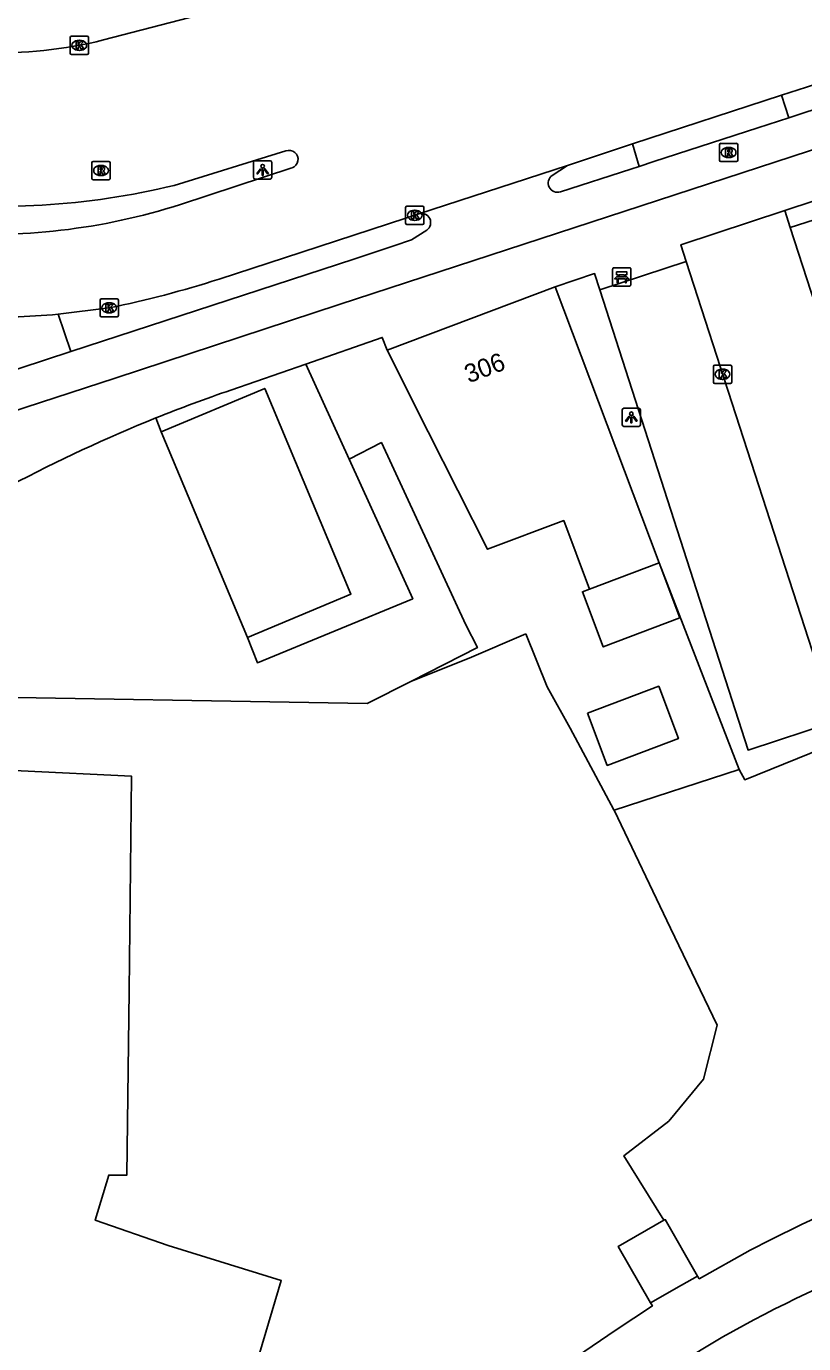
# Model space of a CAD drawing. Extents: x 163010 to 163853, y 382793 to 383982.
# Drawn here: x 163172.3 to 163214.8, y 383532.5 to 383604.5 of the extents above; entities that cross this region are included whole.
import ezdxf

# ---------------------------------------------------------------- set-up
doc = ezdxf.new("R2010")
doc.units = 0
for name, color, linetype in [('IMGEO_Bank', 7, 'Continuous'), ('IMGEO_Berm_open', 7, 'Continuous'), ('IMGEO_Fietspad_open', 7, 'Continuous'), ('IMGEO_Groenvoorziening', 7, 'Continuous'), ('IMGEO_Hek', 7, 'Continuous'), ('IMGEO_Kolk', 7, 'Continuous'), ('IMGEO_Lage_trafo', 7, 'Continuous'), ('IMGEO_Lichtpunt', 7, 'Continuous'), ('IMGEO_Muur', 7, 'Continuous'), ('IMGEO_Pand', 7, 'Continuous'), ('IMGEO_Pand_nummerreeks', 7, 'Continuous'), ('IMGEO_Parkeervlak_open', 7, 'Continuous'), ('IMGEO_Rijbaan_lokaal_gesloten', 7, 'Continuous'), ('IMGEO_Rijbaan_lokaal_open', 7, 'Continuous'), ('IMGEO_Rioolput', 7, 'Continuous'), ('IMGEO_Verkeerseiland_open', 7, 'Continuous'), ('IMGEO_Voetpad_halfverhard', 7, 'Continuous'), ('IMGEO_Voetpad_open', 7, 'Continuous')]:
    doc.layers.add(name, color=color, linetype=linetype)

msp = doc.modelspace()

# ---------------------------------------------------------------- linework, layer by layer
at = {"layer": 'IMGEO_Bank'}
for p, q in [((163204.37, 383590.379), (163204.37, 383591.22)), ((163204.37, 383591.22), (163204.37, 383590.379)), ((163204.445, 383591.304), (163205.286, 383591.304)), ((163205.286, 383591.304), (163204.445, 383591.304)), ((163205.067, 383590.702), (163204.674, 383590.702)), ((163204.679, 383590.81), (163204.679, 383590.916)), ((163204.723, 383590.916), (163204.723, 383590.81)), ((163205.011, 383590.922), (163204.729, 383590.922)), ((163204.729, 383590.804), (163205.011, 383590.804)), ((163205.017, 383590.81), (163205.017, 383590.916)), ((163205.061, 383590.916), (163205.061, 383590.81)), ((163205.37, 383591.229), (163205.37, 383590.388)), ((163205.37, 383590.388), (163205.37, 383591.229)), ((163205.295, 383590.304), (163204.454, 383590.304)), ((163204.454, 383590.304), (163205.295, 383590.304))]:
    msp.add_line(p, q, dxfattribs=at)
for points in [[(163204.617, 383590.702), (163204.475, 383590.702), (163204.587, 383590.804), (163204.673, 383590.804)], [(163204.673, 383590.922), (163204.587, 383590.922), (163204.587, 383591.083), (163205.15, 383591.083), (163205.15, 383590.922), (163205.067, 383590.922)], [(163204.667, 383590.695), (163204.667, 383590.488), (163204.624, 383590.488), (163204.624, 383590.695)], [(163205.067, 383590.804), (163205.15, 383590.804), (163205.262, 383590.702), (163205.123, 383590.702)], [(163205.117, 383590.695), (163205.117, 383590.488), (163205.073, 383590.488), (163205.073, 383590.695)]]:
    msp.add_lwpolyline(points, dxfattribs=at)
for centre, radius, start, end in [((163204.448, 383591.226), 0.0779, 92.4484, 184.28452), ((163204.448, 383591.226), 0.0779, 92.4484, 184.28452), ((163204.617, 383590.695), 0.00671, 2.89567, 87.10433), ((163204.674, 383590.695), 0.00671, 92.89567, 177.10433), ((163204.672, 383590.915), 0.00671, 2.89567, 87.10433), ((163204.672, 383590.811), 0.00671, 272.89567, 357.10433), ((163204.729, 383590.915), 0.00671, 92.89567, 177.10433), ((163204.729, 383590.811), 0.00671, 182.89567, 267.10433), ((163205.011, 383590.915), 0.00671, 2.89567, 87.10433), ((163205.011, 383590.811), 0.00671, 272.89567, 357.10433), ((163205.068, 383590.915), 0.00671, 92.89567, 177.10433), ((163205.068, 383590.811), 0.00671, 182.89567, 267.10433), ((163205.066, 383590.695), 0.00671, 2.89567, 87.10433), ((163205.123, 383590.695), 0.00671, 92.89567, 177.10433), ((163205.292, 383591.226), 0.0779, 2.4484, 94.28452), ((163205.292, 383591.226), 0.0779, 2.4484, 94.28452), ((163204.448, 383590.382), 0.0779, 182.4484, 274.28452), ((163204.448, 383590.382), 0.0779, 182.4484, 274.28452), ((163205.292, 383590.382), 0.0779, 272.4484, 4.28452), ((163205.292, 383590.382), 0.0779, 272.4484, 4.28452)]:
    msp.add_arc(centre, radius, start, end, dxfattribs=at)
at = {"layer": 'IMGEO_Berm_open'}
msp.add_lwpolyline([(163213.597, 383600.731), (163214, 383599.504)], dxfattribs=at)
at = {"layer": 'IMGEO_Fietspad_open'}
for points in [[(163227.273, 383603.884), (163214, 383599.504)], [(163165.737, 383581.534), (163177.201, 383585.275), (163189.429, 383589.292), (163227.938, 383601.879)], [(163214, 383599.504), (163212.305, 383598.953), (163206.623, 383597.104), (163205.825, 383596.845)], [(163201.071, 383596.353), (163201.91, 383596.897)], [(163205.825, 383596.845), (163205.366, 383596.686), (163201.515, 383595.458)], [(163194.216, 383593.356), (163193.389, 383592.83), (163192.424, 383592.497), (163190.238, 383591.768), (163174.785, 383586.731)], [(163174.785, 383586.731), (163165.182, 383583.588)]]:
    msp.add_lwpolyline(points, dxfattribs=at)
for centre, radius, start, end in [((163201.355, 383595.936), 0.504, 124.23922, 288.53182), ((163193.925, 383593.772), 0.508, 304.98045, 106.77094)]:
    msp.add_arc(centre, radius, start, end, dxfattribs=at)
at = {"layer": 'IMGEO_Groenvoorziening'}
for points in [[(163179.716, 383582.349), (163184.42, 383571.112)], [(163167.542, 383567.909), (163190.955, 383567.498), (163193.383, 383568.73), (163196.982, 383570.557), (163196.354, 383571.794), (163191.745, 383581.753), (163189.98, 383580.853)], [(163206.912, 383575.186), (163211.278, 383563.895)], [(163211.278, 383563.895), (163211.588, 383563.335), (163224.444, 383568.537)], [(163207.169, 383539.271), (163204.989, 383542.801), (163207.436, 383544.678), (163209.327, 383546.99), (163210.082, 383549.931), (163207.536, 383555.238), (163204.446, 383561.681), (163211.278, 383563.895)]]:
    msp.add_lwpolyline(points, dxfattribs=at)
at = {"layer": 'IMGEO_Hek'}
msp.add_lwpolyline([(163204.439, 383561.696), (163204.446, 383561.681), (163207.536, 383555.238), (163210.082, 383549.931), (163209.327, 383546.99), (163207.436, 383544.678), (163204.989, 383542.801), (163207.169, 383539.271)], dxfattribs=at)
at = {"layer": 'IMGEO_Kolk'}
for p, q in [((163174.74, 383603.032), (163174.74, 383603.884)), ((163174.815, 383603.958), (163175.667, 383603.958)), ((163175.228, 383603.738), (163175.253, 383603.738)), ((163175.741, 383603.884), (163175.741, 383603.032)), ((163175.667, 383602.958), (163174.815, 383602.958)), ((163175.251, 383603.178), (163175.226, 383603.178)), ((163193.064, 383593.747), (163193.064, 383594.599)), ((163193.139, 383594.673), (163193.991, 383594.673)), ((163193.552, 383594.453), (163193.577, 383594.453)), ((163194.065, 383594.599), (163194.065, 383593.747)), ((163193.991, 383593.673), (163193.139, 383593.673)), ((163193.575, 383593.893), (163193.55, 383593.893)), ((163176.374, 383588.692), (163176.374, 383589.544)), ((163176.449, 383589.618), (163177.301, 383589.618)), ((163176.862, 383589.398), (163176.887, 383589.398)), ((163177.375, 383589.544), (163177.375, 383588.692)), ((163177.301, 383588.618), (163176.449, 383588.618)), ((163176.885, 383588.838), (163176.86, 383588.838)), ((163209.874, 383585.063), (163209.874, 383585.915)), ((163209.949, 383585.989), (163210.801, 383585.989)), ((163210.362, 383585.769), (163210.387, 383585.769)), ((163210.875, 383585.915), (163210.875, 383585.063)), ((163210.801, 383584.989), (163209.949, 383584.989)), ((163210.385, 383585.209), (163210.36, 383585.209))]:
    msp.add_line(p, q, dxfattribs=at)
for points in [[(163174.74, 383603.032), (163174.74, 383603.884)], [(163174.815, 383603.958), (163175.667, 383603.958)], [(163175.061, 383603.658), (163175.184, 383603.658), (163175.184, 383603.507), (163175.314, 383603.658), (163175.478, 383603.658), (163175.332, 383603.507), (163175.485, 383603.258), (163175.333, 383603.258), (163175.248, 383603.422), (163175.184, 383603.355), (163175.184, 383603.258), (163175.061, 383603.258), (163175.061, 383603.658)], [(163175.741, 383603.884), (163175.741, 383603.032)], [(163175.667, 383602.958), (163174.815, 383602.958)], [(163193.064, 383593.747), (163193.064, 383594.599)], [(163193.139, 383594.673), (163193.991, 383594.673)], [(163193.385, 383594.373), (163193.508, 383594.373), (163193.508, 383594.222), (163193.638, 383594.373), (163193.802, 383594.373), (163193.656, 383594.222), (163193.809, 383593.973), (163193.657, 383593.973), (163193.572, 383594.137), (163193.508, 383594.07), (163193.508, 383593.973), (163193.385, 383593.973), (163193.385, 383594.373)], [(163194.065, 383594.599), (163194.065, 383593.747)], [(163193.991, 383593.673), (163193.139, 383593.673)], [(163176.374, 383588.692), (163176.374, 383589.544)], [(163176.449, 383589.618), (163177.301, 383589.618)], [(163176.695, 383589.318), (163176.818, 383589.318), (163176.818, 383589.167), (163176.948, 383589.318), (163177.112, 383589.318), (163176.966, 383589.167), (163177.119, 383588.918), (163176.967, 383588.918), (163176.882, 383589.082), (163176.818, 383589.015), (163176.818, 383588.918), (163176.695, 383588.918), (163176.695, 383589.318)], [(163177.375, 383589.544), (163177.375, 383588.692)], [(163177.301, 383588.618), (163176.449, 383588.618)], [(163209.874, 383585.063), (163209.874, 383585.915)], [(163209.949, 383585.989), (163210.801, 383585.989)], [(163210.195, 383585.689), (163210.318, 383585.689), (163210.318, 383585.538), (163210.448, 383585.689), (163210.612, 383585.689), (163210.466, 383585.538), (163210.619, 383585.289), (163210.467, 383585.289), (163210.382, 383585.453), (163210.318, 383585.386), (163210.318, 383585.289), (163210.195, 383585.289), (163210.195, 383585.689)], [(163210.875, 383585.915), (163210.875, 383585.063)], [(163210.801, 383584.989), (163209.949, 383584.989)]]:
    msp.add_lwpolyline(points, dxfattribs=at)
for centre, start, end in [((163174.817, 383603.882), 91.55205, 178.44795), ((163174.817, 383603.882), 91.55205, 178.44795), ((163175.665, 383603.882), 1.55205, 88.44795), ((163175.665, 383603.882), 1.55205, 88.44795), ((163174.817, 383603.034), 181.55205, 268.44795), ((163174.817, 383603.034), 181.55205, 268.44795), ((163175.665, 383603.034), 271.55205, 358.44795), ((163175.665, 383603.034), 271.55205, 358.44795), ((163193.141, 383594.597), 91.55205, 178.44795), ((163193.141, 383594.597), 91.55205, 178.44795), ((163193.989, 383594.597), 1.55205, 88.44795), ((163193.989, 383594.597), 1.55205, 88.44795), ((163193.141, 383593.749), 181.55205, 268.44795), ((163193.141, 383593.749), 181.55205, 268.44795), ((163193.989, 383593.749), 271.55205, 358.44795), ((163193.989, 383593.749), 271.55205, 358.44795), ((163176.451, 383589.542), 91.55205, 178.44795), ((163176.451, 383589.542), 91.55205, 178.44795), ((163177.299, 383589.542), 1.55205, 88.44795), ((163177.299, 383589.542), 1.55205, 88.44795), ((163176.451, 383588.694), 181.55205, 268.44795), ((163176.451, 383588.694), 181.55205, 268.44795), ((163177.299, 383588.694), 271.55205, 358.44795), ((163177.299, 383588.694), 271.55205, 358.44795), ((163209.951, 383585.913), 91.55205, 178.44795), ((163209.951, 383585.913), 91.55205, 178.44795), ((163210.799, 383585.913), 1.55205, 88.44795), ((163210.799, 383585.913), 1.55205, 88.44795), ((163209.951, 383585.065), 181.55205, 268.44795), ((163209.951, 383585.065), 181.55205, 268.44795), ((163210.799, 383585.065), 271.55205, 358.44795), ((163210.799, 383585.065), 271.55205, 358.44795)]:
    msp.add_arc(centre, 0.0765, start, end, dxfattribs=at)
for centre, major_axis, ratio, start_param, end_param in [((163175.227, 383603.458), (-0.387, 0.002), 0.722429, 4.712389, 7.853982), ((163175.252, 383603.458), (-0.39, 0.002), 0.717154, 1.570796, 4.712389), ((163193.551, 383594.173), (-0.387, 0.002), 0.722429, 4.712389, 7.853982), ((163193.576, 383594.173), (-0.39, 0.002), 0.717154, 1.570796, 4.712389), ((163176.861, 383589.118), (-0.387, 0.002), 0.722429, 4.712389, 7.853982), ((163176.886, 383589.118), (-0.39, 0.002), 0.717154, 1.570796, 4.712389), ((163210.361, 383585.489), (-0.387, 0.002), 0.722429, 4.712389, 7.853982), ((163210.386, 383585.489), (-0.39, 0.002), 0.717154, 1.570796, 4.712389)]:
    msp.add_ellipse(centre, major_axis=major_axis, ratio=ratio, start_param=start_param, end_param=end_param, dxfattribs=at)
at = {"layer": 'IMGEO_Lage_trafo'}
for points in [[(163207.169, 383539.271), (163204.674, 383537.843), (163206.44, 383534.758)], [(163209.009, 383536.228), (163207.243, 383539.313), (163207.169, 383539.271)], [(163209.009, 383536.228), (163208.124, 383535.721), (163206.44, 383534.758)]]:
    msp.add_lwpolyline(points, dxfattribs=at)
at = {"layer": 'IMGEO_Lichtpunt'}
for p, q in [((163185.657, 383597.151), (163184.849, 383597.151)), ((163185.657, 383597.151), (163184.849, 383597.151)), ((163184.755, 383597.056), (163184.755, 383596.249)), ((163184.755, 383597.056), (163184.755, 383596.249)), ((163185.751, 383596.249), (163185.751, 383597.056)), ((163185.751, 383596.249), (163185.751, 383597.056)), ((163184.849, 383596.155), (163185.657, 383596.155)), ((163184.849, 383596.155), (163185.657, 383596.155)), ((163204.896, 383583.538), (163204.896, 383582.731)), ((163204.896, 383583.538), (163204.896, 383582.731)), ((163205.798, 383583.633), (163204.99, 383583.633)), ((163205.798, 383583.633), (163204.99, 383583.633)), ((163205.892, 383582.731), (163205.892, 383583.538)), ((163205.892, 383582.731), (163205.892, 383583.538)), ((163204.99, 383582.637), (163205.798, 383582.637)), ((163204.99, 383582.637), (163205.798, 383582.637))]:
    msp.add_line(p, q, dxfattribs=at)
for points in [[(163185.129, 383596.72), (163185.168, 383596.692), (163184.98, 383596.43), (163184.942, 383596.457), (163185.129, 383596.72)], [(163185.231, 383596.672), (163185.278, 383596.672), (163185.278, 383596.35), (163185.231, 383596.35), (163185.231, 383596.672)], [(163185.341, 383596.692), (163185.379, 383596.719), (163185.566, 383596.457), (163185.527, 383596.429), (163185.341, 383596.692)], [(163205.27, 383583.202), (163205.309, 383583.174), (163205.121, 383582.912), (163205.083, 383582.939), (163205.27, 383583.202)], [(163205.372, 383583.154), (163205.419, 383583.154), (163205.419, 383582.832), (163205.372, 383582.832), (163205.372, 383583.154)], [(163205.482, 383583.174), (163205.52, 383583.201), (163205.707, 383582.939), (163205.668, 383582.911), (163205.482, 383583.174)]]:
    msp.add_lwpolyline(points, dxfattribs=at)
for centre in [(163185.254, 383596.854), (163205.395, 383583.336)]:
    msp.add_circle(centre, 0.0994, dxfattribs=at)
for centre, start, end in [((163184.849, 383597.056), 90, 180), ((163184.849, 383597.056), 90, 180), ((163185.657, 383597.056), 0, 90), ((163185.657, 383597.056), 0, 90), ((163184.849, 383596.249), 180, 270), ((163184.849, 383596.249), 180, 270), ((163185.657, 383596.249), 270, 0), ((163185.657, 383596.249), 270, 360), ((163204.99, 383583.538), 90, 180), ((163204.99, 383583.538), 90, 180), ((163205.798, 383583.538), 0, 90), ((163205.798, 383583.538), 0, 90), ((163204.99, 383582.731), 180, 270), ((163204.99, 383582.731), 180, 270), ((163205.798, 383582.731), 270, 0), ((163205.798, 383582.731), 270, 360)]:
    msp.add_arc(centre, 0.0946, start, end, dxfattribs=at)
at = {"layer": 'IMGEO_Muur'}
for points in [[(163193.383, 383568.73), (163196.537, 383569.982), (163199.633, 383571.307)], [(163199.633, 383571.307), (163200.798, 383568.411), (163202.047, 383566.163), (163204.439, 383561.696)]]:
    msp.add_lwpolyline(points, dxfattribs=at)
at = {"layer": 'IMGEO_Pand'}
for points in [[(163201.234, 383590.272), (163192.05, 383586.814)], [(163206.912, 383575.186), (163201.234, 383590.272)], [(163192.05, 383586.814), (163194.304, 383582.35), (163197.537, 383575.929), (163201.702, 383577.497), (163203.112, 383573.754)], [(163203.112, 383573.754), (163202.721, 383573.607), (163203.855, 383570.595), (163208.046, 383572.174), (163206.912, 383575.186)], [(163203.112, 383573.754), (163206.912, 383575.186)], [(163203.004, 383566.983), (163204.081, 383564.125), (163207.966, 383565.589), (163206.889, 383568.447), (163203.004, 383566.983)], [(163167.447, 383563.91), (163172.06, 383563.83), (163178.094, 383563.53), (163177.964, 383551.81), (163177.836, 383541.731), (163176.846, 383541.744), (163176.112, 383539.277), (163180.096, 383537.897), (163186.27, 383535.979), (163183.553, 383526.844), (163168.108, 383531.398), (163167.964, 383531.44), (163167.285, 383531.627)]]:
    msp.add_lwpolyline(points, dxfattribs=at)
at = {"layer": 'IMGEO_Parkeervlak_open'}
for points in [[(163218.848, 383595.029), (163214.068, 383593.5)], [(163216.524, 383566.513), (163211.77, 383564.96), (163203.671, 383590.093)]]:
    msp.add_lwpolyline(points, dxfattribs=at)
at = {"layer": 'IMGEO_Rijbaan_lokaal_gesloten'}
for points in [[(163213.597, 383600.731), (163214.956, 383601.18), (163233.054, 383607.14), (163236.408, 383608.071), (163243.205, 383609.62)], [(163176.564, 383603.756), (163195.768, 383608.743)], [(163205.454, 383598.071), (163213.597, 383600.731)], [(163201.91, 383596.897), (163205.454, 383598.071)], [(163180.43, 383595.807), (163186.523, 383597.692)], [(163186.858, 383596.763), (163180.763, 383594.766)], [(163201.91, 383596.897), (163193.778, 383594.259)], [(163182.874, 383590.684), (163187.392, 383592.153), (163193.078, 383594.015), (163193.778, 383594.259)], [(163174.082, 383588.77), (163176.875, 383589.119)]]:
    msp.add_lwpolyline(points, dxfattribs=at)
for centre, radius, start, end in [((163170.997, 383625.61), 22.552, 250.7566, 284.2926), ((163186.696, 383597.229), 0.494, 289.20833, 110.45056), ((163170.936, 383634.883), 40.213, 262.84894, 283.65603), ((163170.292, 383627.431), 34.303, 265.42545, 287.77367), ((163165.659, 383644.391), 56.399, 281.47047, 287.77205), ((163170.436, 383629.239), 40.633, 268.16016, 275.14868)]:
    msp.add_arc(centre, radius, start, end, dxfattribs=at)
at = {"layer": 'IMGEO_Rijbaan_lokaal_open'}
for points in [[(163208.381, 383591.645), (163208.099, 383592.565), (163213.777, 383594.426)], [(163214.068, 383593.5), (163213.777, 383594.426)], [(163222.22, 383568.373), (163214.068, 383593.5)], [(163216.524, 383566.513), (163208.381, 383591.645)]]:
    msp.add_lwpolyline(points, dxfattribs=at)
msp.add_arc((163241.012, 383479.628), 61.439, 112.67834, 131.8916, dxfattribs=at)
at = {"layer": 'IMGEO_Rioolput'}
for p, q in [((163210.207, 383597.178), (163210.207, 383598.03)), ((163210.282, 383598.104), (163211.134, 383598.104)), ((163210.695, 383597.884), (163210.72, 383597.884)), ((163211.208, 383598.03), (163211.208, 383597.178)), ((163210.718, 383597.324), (163210.693, 383597.324)), ((163175.927, 383596.192), (163175.927, 383597.044)), ((163176.002, 383597.118), (163176.854, 383597.118)), ((163176.415, 383596.898), (163176.44, 383596.898)), ((163176.928, 383597.044), (163176.928, 383596.192)), ((163211.134, 383597.104), (163210.282, 383597.104)), ((163176.854, 383596.118), (163176.002, 383596.118)), ((163176.438, 383596.338), (163176.413, 383596.338))]:
    msp.add_line(p, q, dxfattribs=at)
for points in [[(163210.207, 383597.178), (163210.207, 383598.03)], [(163210.282, 383598.104), (163211.134, 383598.104)], [(163211.208, 383598.03), (163211.208, 383597.178)], [(163210.796, 383597.802), (163210.544, 383597.804), (163210.544, 383597.404)], [(163210.544, 383597.404), (163210.668, 383597.404), (163210.668, 383597.566), (163210.679, 383597.566)], [(163210.722, 383597.723), (163210.668, 383597.723), (163210.668, 383597.642)], [(163210.668, 383597.642), (163210.72, 383597.642)], [(163210.726, 383597.537), (163210.797, 383597.404), (163210.937, 383597.404), (163210.872, 383597.53)], [(163175.927, 383596.192), (163175.927, 383597.044)], [(163176.002, 383597.118), (163176.854, 383597.118)], [(163176.516, 383596.816), (163176.264, 383596.818), (163176.264, 383596.418)], [(163176.264, 383596.418), (163176.388, 383596.418), (163176.388, 383596.58), (163176.399, 383596.58)], [(163176.442, 383596.737), (163176.388, 383596.737), (163176.388, 383596.656)], [(163176.388, 383596.656), (163176.44, 383596.656)], [(163176.446, 383596.551), (163176.517, 383596.418), (163176.657, 383596.418), (163176.592, 383596.544)], [(163176.928, 383597.044), (163176.928, 383596.192)], [(163211.134, 383597.104), (163210.282, 383597.104)], [(163176.854, 383596.118), (163176.002, 383596.118)]]:
    msp.add_lwpolyline(points, dxfattribs=at)
for centre, radius, start, end in [((163210.284, 383598.028), 0.0765, 91.55205, 178.44795), ((163210.284, 383598.028), 0.0765, 91.55205, 178.44795), ((163211.132, 383598.028), 0.0765, 1.55205, 88.44795), ((163211.132, 383598.028), 0.0765, 1.55205, 88.44795), ((163210.284, 383597.18), 0.0765, 181.55205, 268.44795), ((163210.284, 383597.18), 0.0765, 181.55205, 268.44795), ((163210.678, 383597.513), 0.0533, 26.02933, 88.69889), ((163210.704, 383597.831), 0.19, 274.7715, 282.96867), ((163210.728, 383597.627), 0.0964, 77.00612, 93.18647), ((163210.742, 383597.684), 0.0378, 276.66336, 79.67722), ((163210.795, 383597.692), 0.109, 350.36119, 89.41601), ((163210.793, 383597.692), 0.112, 277.58423, 350.98172), ((163210.777, 383597.477), 0.108, 29.51342, 73.79051), ((163211.132, 383597.18), 0.0765, 271.55205, 358.44795), ((163211.132, 383597.18), 0.0765, 271.55205, 358.44795), ((163176.004, 383597.042), 0.0765, 91.55205, 178.44795), ((163176.004, 383597.042), 0.0765, 91.55205, 178.44795), ((163176.398, 383596.527), 0.0533, 26.02933, 88.69889), ((163176.424, 383596.845), 0.19, 274.7715, 282.96867), ((163176.448, 383596.641), 0.0964, 77.00612, 93.18647), ((163176.462, 383596.698), 0.0378, 276.66336, 79.67722), ((163176.515, 383596.706), 0.109, 350.36119, 89.41601), ((163176.513, 383596.706), 0.112, 277.58423, 350.98172), ((163176.497, 383596.491), 0.108, 29.51342, 73.79051), ((163176.852, 383597.042), 0.0765, 1.55205, 88.44795), ((163176.852, 383597.042), 0.0765, 1.55205, 88.44795), ((163176.004, 383596.194), 0.0765, 181.55205, 268.44795), ((163176.004, 383596.194), 0.0765, 181.55205, 268.44795), ((163176.852, 383596.194), 0.0765, 271.55205, 358.44795), ((163176.852, 383596.194), 0.0765, 271.55205, 358.44795)]:
    msp.add_arc(centre, radius, start, end, dxfattribs=at)
for centre, major_axis, ratio, start_param, end_param in [((163210.694, 383597.604), (-0.387, 0.002), 0.722429, 4.712389, 7.853982), ((163210.719, 383597.604), (-0.39, 0.002), 0.717154, 1.570796, 4.712389), ((163176.414, 383596.618), (-0.387, 0.002), 0.722429, 4.712389, 7.853982), ((163176.439, 383596.618), (-0.39, 0.002), 0.717154, 1.570796, 4.712389)]:
    msp.add_ellipse(centre, major_axis=major_axis, ratio=ratio, start_param=start_param, end_param=end_param, dxfattribs=at)
at = {"layer": 'IMGEO_Verkeerseiland_open'}
for points in [[(163205.825, 383596.845), (163205.454, 383598.071)], [(163174.082, 383588.77), (163174.785, 383586.731)]]:
    msp.add_lwpolyline(points, dxfattribs=at)
at = {"layer": 'IMGEO_Voetpad_halfverhard'}
for points in [[(163189.98, 383580.853), (163187.611, 383586.048)], [(163179.716, 383582.349), (163185.368, 383584.716), (163190.073, 383573.479), (163184.42, 383571.112)], [(163179.424, 383583.1), (163179.716, 383582.349)], [(163184.42, 383571.112), (163184.97, 383569.73), (163193.457, 383573.221), (163189.98, 383580.853)]]:
    msp.add_lwpolyline(points, dxfattribs=at)
at = {"layer": 'IMGEO_Voetpad_open'}
for points in [[(163213.777, 383594.426), (163218.524, 383595.998)], [(163203.671, 383590.093), (163208.381, 383591.645)], [(163201.234, 383590.272), (163203.382, 383590.989), (163203.671, 383590.093)], [(163187.611, 383586.048), (163191.792, 383587.5), (163192.05, 383586.814)], [(163187.611, 383586.048), (163183.519, 383584.626)], [(163216.383, 383539.819), (163214.681, 383539.043), (163213.032, 383538.22), (163211.882, 383537.646), (163209.098, 383536.078), (163209.009, 383536.228)], [(163206.44, 383534.758), (163206.545, 383534.594), (163204.503, 383533.255), (163202.445, 383531.842), (163201.084, 383530.863), (163200.419, 383530.385), (163198.367, 383528.885), (163197.068, 383527.832), (163193.963, 383524.726)]]:
    msp.add_lwpolyline(points, dxfattribs=at)
for centre, radius, start, end in [((163210.595, 383505.71), 83.432, 108.93716, 111.93862), ((163210.724, 383505.358), 83.806, 111.93025, 117.92503)]:
    msp.add_arc(centre, radius, start, end, dxfattribs=at)

# ---------------------------------------------------------------- texts
at = {"layer": 'IMGEO_Pand_nummerreeks'}
msp.add_text('306', height=1, rotation=20.63258, dxfattribs=at).set_placement((163196.508, 383584.988))

doc.saveas('drawing.dxf')
